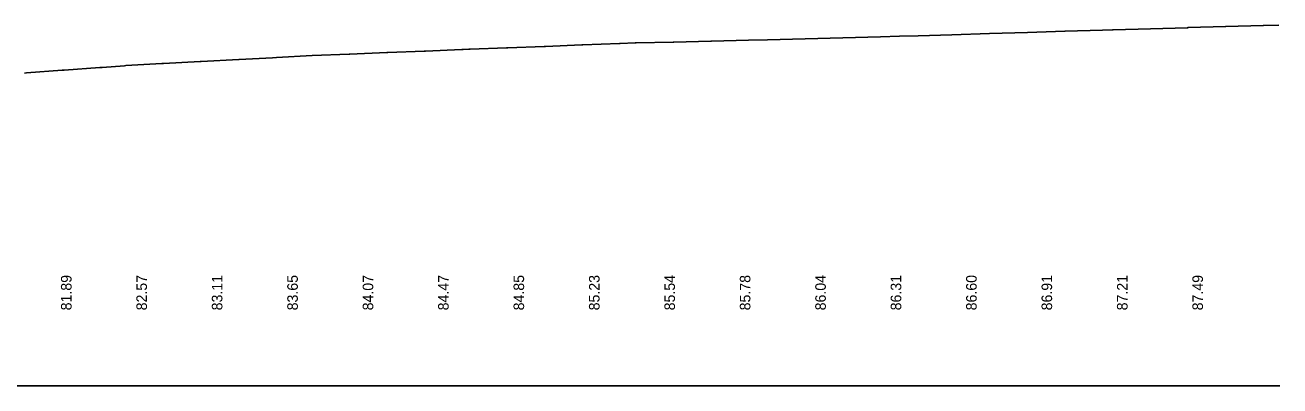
# Model space of a CAD drawing. Extents: x 2526761 to 2530854, y 882903 to 888012.
# Drawn here: x 2527707 to 2528539, y 886362 to 886601 of the extents above; entities that cross this region are included whole.
import ezdxf

# ---------------------------------------------------------------- set-up
doc = ezdxf.new("R2010")
doc.units = 0
for name, color, linetype in [('RD_DDB_Profile_EX', 7, 'Continuous'), ('RD_DDB_StripGrade', 7, 'Continuous'), ('RD_GPK_Profile_Cell', 7, 'Continuous')]:
    doc.layers.add(name, color=color, linetype=linetype)

msp = doc.modelspace()

# ---------------------------------------------------------------- linework, layer by layer
at = {"layer": 'RD_DDB_Profile_EX'}
for points in [[(2528186.65, 886590.93), (2528199.24, 886591.23), (2528224.24, 886591.9), (2528249.24, 886592.58), (2528274.24, 886593.26), (2528286.85, 886593.6), (2528299.26, 886593.93), (2528321.45, 886594.53), (2528346.52, 886595.3), (2528371.6, 886596.08), (2528396.33, 886596.85), (2528396.67, 886596.86), (2528421.33, 886597.63), (2528428.02, 886597.84), (2528428.45, 886597.85), (2528453.19, 886598.54), (2528477.79, 886599.23), (2528478.18, 886599.24), (2528502.81, 886599.93), (2528503.18, 886599.94), (2528527.82, 886600.62), (2528528.18, 886600.63), (2528538.15, 886600.91)], [(2527706.76, 886569.19), (2527708.15, 886569.28), (2527731.79, 886571.02), (2527733.15, 886571.12), (2527756.81, 886572.86), (2527758.15, 886572.95), (2527773.07, 886574.05), (2527773.91, 886574.11), (2527797.91, 886575.4), (2527798.9, 886575.46), (2527823.23, 886576.77), (2527823.96, 886576.81), (2527848.85, 886578.14), (2527849.16, 886578.16), (2527871.19, 886579.35), (2527873.9, 886579.5), (2527897.51, 886580.77), (2527922.02, 886581.75), (2527922.51, 886581.77), (2527946.88, 886582.75), (2527947.52, 886582.77), (2527971.75, 886583.74), (2527972.52, 886583.77), (2527996.62, 886584.73), (2527997.56, 886584.77), (2528001.25, 886584.92), (2528002.18, 886584.96), (2528026.26, 886585.87), (2528027.11, 886585.91), (2528051.27, 886586.82), (2528052.04, 886586.85), (2528076.27, 886587.76), (2528076.97, 886587.8), (2528101.28, 886588.71), (2528101.59, 886588.73), (2528111.65, 886589.1), (2528112.24, 886589.13), (2528136.65, 886589.71), (2528137.16, 886589.73), (2528161.65, 886590.32), (2528162.08, 886590.34), (2528186.65, 886590.93)]]:
    msp.add_lwpolyline(points, dxfattribs=at)
at = {"layer": 'RD_GPK_Profile_Cell'}
msp.add_line((2526838.95, 886362.08), (2528538.95, 886362.08), dxfattribs=at)

# ---------------------------------------------------------------- texts
at = {"layer": 'RD_DDB_StripGrade'}
for s, p in [('81.89', (2527737.95, 886412.08)), ('82.57', (2527787.95, 886412.08)), ('83.11', (2527837.95, 886412.08)), ('83.65', (2527887.95, 886412.08)), ('84.07', (2527937.95, 886412.08)), ('84.47', (2527987.95, 886412.08)), ('84.85', (2528037.95, 886412.08)), ('85.23', (2528087.95, 886412.08)), ('85.54', (2528137.95, 886412.08)), ('85.78', (2528187.95, 886412.08)), ('86.04', (2528237.95, 886412.08)), ('86.31', (2528287.95, 886412.08)), ('86.60', (2528337.95, 886412.08)), ('86.91', (2528387.95, 886412.08)), ('87.21', (2528437.95, 886412.08)), ('87.49', (2528487.95, 886412.08))]:
    msp.add_text(s, height=7, rotation=90, dxfattribs=at).set_placement(p)

doc.saveas('drawing.dxf')
